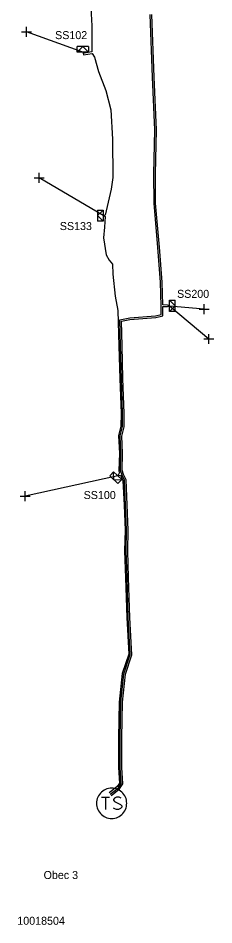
# Model space of a CAD drawing. Extents: x -763093 to -760976, y -1155572 to -1152009.
# Drawn here: x -762774.6 to -762750.1, y -1152519.2 to -1152405.9 of the extents above; entities that cross this region are included whole.
import ezdxf

# ---------------------------------------------------------------- set-up
doc = ezdxf.new("R2010")
doc.units = 0
for name, color, linetype in [('Vrstva 1', 7, 'Continuous'), ('Vrstva 25', 7, 'Continuous'), ('Vrstva 26', 7, 'Continuous'), ('Vrstva 27', 7, 'Continuous'), ('Vrstva 31', 7, 'Continuous'), ('Vrstva 33', 7, 'Continuous'), ('Vrstva 34', 7, 'Continuous'), ('Vrstva 5', 7, 'Continuous'), ('Vrstva 59', 7, 'Continuous'), ('Vrstva 6', 7, 'Continuous'), ('Vrstva 9', 7, 'Continuous')]:
    doc.layers.add(name, color=color, linetype=linetype)

# ---------------------------------------------------------------- blocks, each defined once
blk = doc.blocks.new('NN800')
at = {"layer": 'Vrstva 1'}
for points in [[(-0.44, 0.44), (0.44, -0.44)], [(-0.44, -0.44), (0.44, 0.44)]]:
    blk.add_lwpolyline(points, dxfattribs=at)
blk = doc.blocks.new('NN630')
at = {"layer": 'Vrstva 9'}
for points in [[(0, -0.7), (-0.7, 0)], [(-0.7, -0.7), (-0.7, 0), (0.7, 0), (0.7, -0.7)], [(-0.7, -0.7), (0.7, -0.7)], [(0, -0.7), (0.7, 0)]]:
    blk.add_lwpolyline(points, dxfattribs=at)
blk = doc.blocks.new('NN610')
at = {"layer": 'Vrstva 6'}
for points in [[(1.88, 0), (1.87, 0.2), (1.84, 0.39), (1.79, 0.58), (1.72, 0.77), (1.63, 0.94), (1.52, 1.11), (1.4, 1.26), (1.26, 1.4), (1.1, 1.53), (0.94, 1.63), (0.76, 1.72), (0.58, 1.8), (0.19, 1.88), (0.19, 1.88), (-0.01, 1.89), (-0.21, 1.88), (-0.4, 1.85), (-0.59, 1.8), (-0.78, 1.72), (-0.95, 1.63), (-1.12, 1.53), (-1.27, 1.4), (-1.41, 1.26), (-1.54, 1.11), (-1.64, 0.94), (-1.73, 0.77), (-1.8, 0.58), (-1.86, 0.39), (-1.89, 0.2), (-1.9, 0), (-1.89, -0.2), (-1.86, -0.39), (-1.8, -0.58), (-1.73, -0.77), (-1.64, -0.95), (-1.54, -1.11), (-1.41, -1.27), (-1.27, -1.41), (-1.12, -1.53), (-0.95, -1.64), (-0.78, -1.73), (-0.59, -1.8), (-0.4, -1.85), (-0.21, -1.88), (-0.01, -1.89), (0.19, -1.88), (0.39, -1.85), (0.58, -1.8), (0.76, -1.73), (0.94, -1.64), (1.1, -1.53), (1.26, -1.41), (1.4, -1.27), (1.52, -1.11), (1.63, -0.95), (1.72, -0.77), (1.79, -0.58), (1.84, -0.39), (1.87, -0.2), (1.88, 0)], [(-1.27, 0.78), (-0.26, 0.78)], [(-0.76, 0.78), (-0.76, -0.79)], [(1.19, 0.66), (0.94, 0.78), (0.62, 0.78), (0.37, 0.66), (0.24, 0.47), (0.24, 0.4), (0.37, 0.22), (1.12, -0.16), (1.25, -0.32), (1.25, -0.48), (1.12, -0.67), (0.87, -0.79), (0.62, -0.79), (0.49, -0.73), (0.24, -0.6)]]:
    blk.add_lwpolyline(points, dxfattribs=at)

msp = doc.modelspace()

# ---------------------------------------------------------------- linework, layer by layer
at = {"layer": 'Vrstva 5'}
for points in [[(-762765.56, -1152403.85), (-762765.41, -1152406.87), (-762765.4, -1152410.13), (-762766.32, -1152410.29), (-762766.53, -1152410.14), (-762766.42, -1152410.51), (-762765.34, -1152410.32), (-762765.05, -1152410.8), (-762764.57, -1152412.56), (-762763.65, -1152414.95), (-762763.02, -1152417.35), (-762762.81, -1152421.04), (-762762.77, -1152425.84), (-762762.97, -1152427.26), (-762763.71, -1152430.51), (-762763.99, -1152430.59), (-762763.74, -1152430.71), (-762763.81, -1152432.02), (-762763.95, -1152433.36), (-762763.62, -1152435.49), (-762763.22, -1152436.17), (-762762.81, -1152436.65), (-762762.76, -1152437.88), (-762762.48, -1152440.65), (-762762.14, -1152442.45), (-762762, -1152446.87), (-762761.9, -1152450.97), (-762761.74, -1152455.3), (-762761.75, -1152456.91), (-762762.05, -1152458.09), (-762761.95, -1152460.25), (-762762, -1152462.47), (-762761.93, -1152462.67), (-762762.16, -1152463.08), (-762761.82, -1152463.03), (-762761.52, -1152463.69), (-762761.37, -1152466.76), (-762761.24, -1152469.89), (-762761.29, -1152472.46), (-762761.19, -1152475.83), (-762761.03, -1152480.81), (-762760.78, -1152485.39), (-762761.6, -1152487.81), (-762761.96, -1152491.37), (-762762.04, -1152495.86), (-762762.06, -1152499.56), (-762761.92, -1152501.49), (-762762.22, -1152501.93), (-762762.89, -1152502.48), (-762763.21, -1152502.71)], [(-762763.09, -1152502.87), (-762762.77, -1152502.64), (-762762.07, -1152502.07), (-762761.72, -1152501.54), (-762761.86, -1152499.55), (-762761.84, -1152495.86), (-762761.76, -1152491.38), (-762761.4, -1152487.85), (-762760.58, -1152485.42), (-762760.83, -1152480.8), (-762760.99, -1152475.82), (-762761.09, -1152472.46), (-762761.04, -1152469.89), (-762761.17, -1152466.75), (-762761.32, -1152463.64), (-762761.61, -1152463), (-762761.8, -1152462.44), (-762761.75, -1152460.25), (-762761.85, -1152458.11), (-762761.55, -1152456.94), (-762761.54, -1152455.3), (-762761.7, -1152450.96), (-762761.8, -1152446.86), (-762761.9, -1152443.62), (-762760.65, -1152443.37), (-762757.41, -1152443.1), (-762756.71, -1152442.93), (-762756.71, -1152441.85), (-762756.79, -1152438.92), (-762757.12, -1152434.56), (-762757.61, -1152429.01), (-762757.62, -1152425.4), (-762757.51, -1152419.87), (-762757.8, -1152413.28), (-762758.08, -1152405.45)], [(-762762.97, -1152503.03), (-762762.65, -1152502.8), (-762761.92, -1152502.21), (-762761.52, -1152501.59), (-762761.66, -1152499.54), (-762761.64, -1152495.86), (-762761.56, -1152491.39), (-762761.2, -1152487.89), (-762760.38, -1152485.45), (-762760.63, -1152480.79), (-762760.79, -1152475.81), (-762760.89, -1152472.46), (-762760.84, -1152469.89), (-762760.97, -1152466.74), (-762761.12, -1152463.59), (-762761.42, -1152462.93), (-762761.6, -1152462.41), (-762761.55, -1152460.25), (-762761.65, -1152458.13), (-762761.35, -1152456.97), (-762761.34, -1152455.3), (-762761.5, -1152450.95), (-762761.6, -1152446.85), (-762761.7, -1152443.78), (-762760.63, -1152443.57), (-762757.37, -1152443.3), (-762756.51, -1152443.09), (-762756.51, -1152441.95), (-762755.91, -1152441.96), (-762755.67, -1152441.87), (-762755.92, -1152441.76), (-762756.51, -1152441.75), (-762756.59, -1152438.9), (-762756.92, -1152434.54), (-762757.41, -1152429.01), (-762757.42, -1152425.4), (-762757.31, -1152419.87), (-762757.6, -1152413.28), (-762757.88, -1152405.45)]]:
    msp.add_lwpolyline(points, dxfattribs=at)
at = {"layer": 'Vrstva 59'}
for points in [[(-762766.53, -1152410.14), (-762773.56, -1152407.63)], [(-762763.99, -1152430.59), (-762772, -1152425.88)], [(-762755.67, -1152441.87), (-762750.75, -1152446)], [(-762755.67, -1152441.87), (-762751.33, -1152442.25)], [(-762762.16, -1152463.08), (-762773.75, -1152465.63)]]:
    msp.add_lwpolyline(points, dxfattribs=at)

# ---------------------------------------------------------------- block references
at = {"layer": 'Vrstva 25'}
msp.add_blockref('NN610', (-762762.91, -1152504.02), dxfattribs=at)
at = {"layer": 'Vrstva 31'}
for p, rotation in [((-762766.53, -1152410.14), 180), ((-762763.99, -1152430.59), -90), ((-762755.67, -1152441.87), 90), ((-762762.16, -1152463.08), -42.85042503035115)]:
    msp.add_blockref('NN630', p, dxfattribs=dict(at, rotation=rotation))
at = {"layer": 'Vrstva 34', "rotation": 45}
for p in [(-762773.56, -1152407.63), (-762772, -1152425.88), (-762751.33, -1152442.26), (-762750.75, -1152446), (-762773.75, -1152465.63)]:
    msp.add_blockref('NN800', p, dxfattribs=at)

# ---------------------------------------------------------------- texts
at = {"layer": 'Vrstva 26'}
msp.add_text('10018504', height=1, dxfattribs=at).set_placement((-762774.72, -1152519.2))
at = {"layer": 'Vrstva 27'}
msp.add_text('Obec 3', height=1, dxfattribs=at).set_placement((-762771.43, -1152513.48))
at = {"layer": 'Vrstva 33'}
for s, p in [('SS102', (-762769.99, -1152408.53)), ('SS133', (-762769.4, -1152432.39)), ('SS200', (-762754.73, -1152440.86)), ('SS100', (-762766.42, -1152466))]:
    msp.add_text(s, height=1, dxfattribs=at).set_placement(p)

doc.saveas('drawing.dxf')
